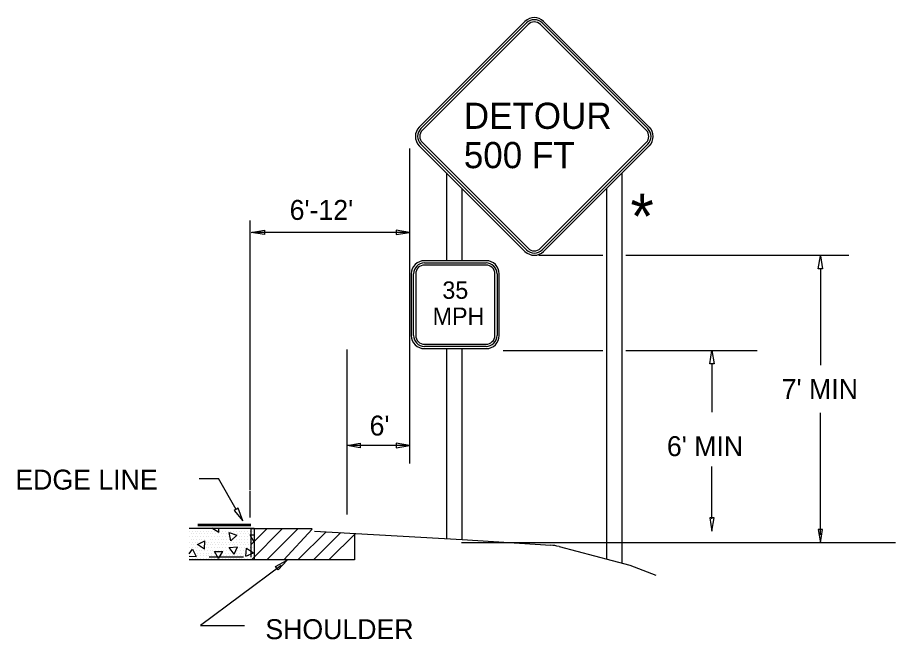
# Model space of a CAD drawing. Extents: x 12.65 to 19.62, y 5.94 to 15.74.
# Drawn here: x 15.864 to 18.505, y 10.963 to 12.834 of the extents above; entities that cross this region are included whole.
import ezdxf

# ---------------------------------------------------------------- set-up
doc = ezdxf.new("R2010")
doc.units = 0
for name, color, linetype in [('DETL-DIMS', 7, 'Continuous'), ('DETL-LINE', 7, 'Continuous'), ('DETL-NOTE', 7, 'Continuous')]:
    doc.layers.add(name, color=color, linetype=linetype)

msp = doc.modelspace()

# ---------------------------------------------------------------- linework, layer by layer
at = {"layer": 'DETL-DIMS'}
for p, q in [((17.0431, 12.4404), (17.0431, 11.4922)), ((16.5641, 11.4122), (16.5641, 12.2237)), ((17.0431, 12.1875), (16.5696, 12.1875)), ((17.4325, 12.1187), (17.6246, 12.1187)), ((17.6944, 12.1187), (18.3653, 12.1187)), ((18.2796, 12.0776), (18.2796, 11.7879)), ((16.8556, 11.3388), (16.8556, 11.8354)), ((17.3252, 11.8319), (17.6246, 11.8319)), ((17.6944, 11.8319), (18.0896, 11.8319)), ((17.9532, 11.7923), (17.9532, 11.6463)), ((18.2796, 11.2776), (18.2796, 11.6448)), ((17.0431, 11.5464), (16.8556, 11.5464)), ((17.9532, 11.3253), (17.9532, 11.4831)), ((16.4107, 11.4467), (16.4686, 11.4467)), ((16.5218, 11.3543), (16.4686, 11.4467)), ((16.5641, 11.3297), (16.5641, 11.4087)), ((16.6572, 11.1852), (16.4146, 11.0046)), ((16.4146, 11.0046), (16.5469, 11.0046))]:
    msp.add_line(p, q, dxfattribs=at)
for points in [[(16.607, 12.194), (16.607, 12.1808), (16.5674, 12.1874)], [(17.0035, 12.1941), (17.0035, 12.1809), (17.0431, 12.1875)], [(18.2862, 12.0776), (18.273, 12.0776), (18.2796, 12.1172)], [(17.9598, 11.7923), (17.9466, 11.7923), (17.9532, 11.8319)], [(16.8952, 11.553), (16.8952, 11.5398), (16.8556, 11.5464)], [(17.0035, 11.553), (17.0035, 11.5398), (17.0431, 11.5464)], [(16.5275, 11.3575), (16.516, 11.351), (16.5415, 11.32)], [(17.9598, 11.3283), (17.9466, 11.3283), (17.9532, 11.2887)], [(18.2862, 11.2934), (18.273, 11.2934), (18.2796, 11.2538)], [(16.648, 11.1719), (16.6398, 11.1823), (16.6752, 11.2013)]]:
    msp.add_lwpolyline(points, close=True, dxfattribs=at)
at = {"layer": 'DETL-LINE'}
for p, q in [((17.3908, 12.8224), (17.0728, 12.5044)), ((17.0775, 12.4998), (17.3954, 12.8177)), ((17.4001, 12.813), (17.0822, 12.495)), ((17.7555, 12.495), (17.4376, 12.813)), ((17.4422, 12.8177), (17.7602, 12.4998)), ((17.7648, 12.5044), (17.4469, 12.8224)), ((17.0728, 12.4483), (17.3908, 12.1303)), ((17.3954, 12.135), (17.0775, 12.453)), ((17.0822, 12.4576), (17.4001, 12.1397)), ((17.4376, 12.1397), (17.7555, 12.4576)), ((17.7602, 12.453), (17.4422, 12.135)), ((17.4469, 12.1303), (17.7648, 12.4483)), ((17.1543, 12.3668), (17.1543, 12.1024)), ((17.6834, 11.1924), (17.6834, 12.3668)), ((17.2021, 12.1024), (17.2021, 12.319)), ((17.6356, 12.319), (17.6356, 11.2049)), ((17.4375, 12.1396), (17.4376, 12.1397)), ((17.2736, 12.1024), (17.0884, 12.1024)), ((17.0884, 12.0958), (17.2736, 12.0958)), ((17.2736, 12.0892), (17.0884, 12.0892)), ((17.0488, 12.0628), (17.0488, 11.8776)), ((17.0554, 11.8776), (17.0554, 12.0628)), ((17.062, 12.0628), (17.062, 11.8776)), ((17.3, 11.8776), (17.3, 12.0628)), ((17.3066, 12.0628), (17.3066, 11.8776)), ((17.3133, 11.8776), (17.3133, 12.0628)), ((17.3, 11.8776), (17.3, 11.8776)), ((17.0884, 11.8511), (17.2736, 11.8511)), ((17.2736, 11.8445), (17.0884, 11.8445)), ((17.0884, 11.8379), (17.2736, 11.8379)), ((17.1543, 11.8379), (17.1543, 11.2664)), ((17.2021, 11.2635), (17.2021, 11.8379)), ((16.5662, 11.3084), (16.4063, 11.3084)), ((16.5662, 11.3064), (16.4063, 11.3064)), ((16.5662, 11.3044), (16.4063, 11.3044)), ((16.576, 11.2968), (16.3805, 11.2968)), ((16.3818, 11.2885), (16.3818, 11.2885)), ((16.386, 11.2802), (16.386, 11.2802)), ((16.3901, 11.2885), (16.3901, 11.2885)), ((16.3942, 11.2802), (16.3942, 11.2802)), ((16.3983, 11.2885), (16.3983, 11.2885)), ((16.4024, 11.2802), (16.4024, 11.2802)), ((16.4066, 11.2885), (16.4066, 11.2885)), ((16.4107, 11.2802), (16.4107, 11.2802)), ((16.4148, 11.2885), (16.4148, 11.2885)), ((16.419, 11.2802), (16.419, 11.2802)), ((16.4231, 11.2885), (16.4231, 11.2885)), ((16.4272, 11.2802), (16.4272, 11.2802)), ((16.4314, 11.2885), (16.4314, 11.2885)), ((16.4355, 11.2802), (16.4355, 11.2802)), ((16.4396, 11.2885), (16.4396, 11.2885)), ((16.4438, 11.2802), (16.4438, 11.2802)), ((16.4479, 11.2885), (16.4479, 11.2885)), ((16.4698, 11.2848), (16.4484, 11.2973)), ((16.4521, 11.2802), (16.4521, 11.2802)), ((16.4562, 11.2885), (16.4562, 11.2885)), ((16.4603, 11.2802), (16.4603, 11.2802)), ((16.4686, 11.2802), (16.4686, 11.2802)), ((16.4698, 11.2848), (16.4698, 11.2968)), ((16.4728, 11.2885), (16.4728, 11.2885)), ((16.4769, 11.2802), (16.4769, 11.2802)), ((16.481, 11.2885), (16.481, 11.2885)), ((16.4852, 11.2802), (16.4852, 11.2802)), ((16.4893, 11.2885), (16.4893, 11.2885)), ((16.4934, 11.2802), (16.4934, 11.2802)), ((16.4976, 11.2885), (16.4976, 11.2885)), ((16.5008, 11.2844), (16.5243, 11.2765)), ((16.5056, 11.26), (16.5008, 11.2844)), ((16.5058, 11.2885), (16.5058, 11.2885)), ((16.5141, 11.2885), (16.5141, 11.2885)), ((16.5182, 11.2802), (16.5182, 11.2802)), ((16.5224, 11.2885), (16.5224, 11.2885)), ((16.5265, 11.2802), (16.5265, 11.2802)), ((16.5306, 11.2885), (16.5306, 11.2885)), ((16.5347, 11.2802), (16.5347, 11.2802)), ((16.5388, 11.2885), (16.5388, 11.2885)), ((16.543, 11.2802), (16.543, 11.2802)), ((16.5471, 11.2885), (16.5471, 11.2885)), ((16.5512, 11.2802), (16.5512, 11.2802)), ((16.5554, 11.2885), (16.5554, 11.2885)), ((16.5595, 11.2802), (16.5595, 11.2802)), ((16.5636, 11.2885), (16.5636, 11.2885)), ((16.5668, 11.2964), (16.7505, 11.2964)), ((16.5668, 11.2484), (16.6149, 11.2964)), ((16.5668, 11.2102), (16.5668, 11.2948)), ((16.5675, 11.2024), (16.6615, 11.2964)), ((16.5678, 11.2802), (16.5678, 11.2802)), ((16.5719, 11.2885), (16.5719, 11.2885)), ((16.576, 11.2968), (16.576, 11.2968)), ((16.576, 11.2968), (16.576, 11.2019)), ((16.6142, 11.2024), (16.7082, 11.2964)), ((16.7501, 11.2947), (16.6653, 11.2024)), ((16.7075, 11.2024), (16.7922, 11.287)), ((16.7542, 11.2024), (16.8363, 11.2846)), ((16.7575, 11.289), (17.2021, 11.2635)), ((16.8008, 11.2024), (16.8804, 11.282)), ((16.878, 11.2831), (16.878, 11.2024)), ((16.3818, 11.2721), (16.3818, 11.2721)), ((16.3818, 11.2555), (16.3818, 11.2555)), ((16.386, 11.2638), (16.386, 11.2638)), ((16.3901, 11.2721), (16.3901, 11.2721)), ((16.3901, 11.2555), (16.3901, 11.2555)), ((16.3942, 11.2638), (16.3942, 11.2638)), ((16.3983, 11.2721), (16.3983, 11.2721)), ((16.3983, 11.2555), (16.3983, 11.2555)), ((16.4024, 11.2638), (16.4024, 11.2638)), ((16.4055, 11.2482), (16.4277, 11.2594)), ((16.4066, 11.2721), (16.4066, 11.2721)), ((16.4066, 11.2555), (16.4066, 11.2555)), ((16.4107, 11.2638), (16.4107, 11.2638)), ((16.4148, 11.2721), (16.4148, 11.2721)), ((16.4148, 11.2555), (16.4148, 11.2555)), ((16.419, 11.2638), (16.419, 11.2638)), ((16.4231, 11.2721), (16.4231, 11.2721)), ((16.4264, 11.2347), (16.4277, 11.2594)), ((16.4272, 11.2638), (16.4272, 11.2638)), ((16.4314, 11.2721), (16.4314, 11.2721)), ((16.4314, 11.2555), (16.4314, 11.2555)), ((16.4396, 11.2721), (16.4396, 11.2721)), ((16.4396, 11.2555), (16.4396, 11.2555)), ((16.4438, 11.2638), (16.4438, 11.2638)), ((16.4479, 11.2721), (16.4479, 11.2721)), ((16.4479, 11.2555), (16.4479, 11.2555)), ((16.4521, 11.2638), (16.4521, 11.2638)), ((16.4562, 11.2721), (16.4562, 11.2721)), ((16.4562, 11.2555), (16.4562, 11.2555)), ((16.4603, 11.2638), (16.4603, 11.2638)), ((16.4645, 11.2721), (16.4645, 11.2721)), ((16.4645, 11.2555), (16.4645, 11.2555)), ((16.4686, 11.2638), (16.4686, 11.2638)), ((16.4728, 11.2721), (16.4728, 11.2721)), ((16.4728, 11.2555), (16.4728, 11.2555)), ((16.4769, 11.2638), (16.4769, 11.2638)), ((16.481, 11.2721), (16.481, 11.2721)), ((16.481, 11.2555), (16.481, 11.2555)), ((16.4852, 11.2638), (16.4852, 11.2638)), ((16.4893, 11.2721), (16.4893, 11.2721)), ((16.4893, 11.2555), (16.4893, 11.2555)), ((16.4934, 11.2638), (16.4934, 11.2638)), ((16.4976, 11.2721), (16.4976, 11.2721)), ((16.4976, 11.2555), (16.4976, 11.2555)), ((16.5017, 11.2638), (16.5017, 11.2638)), ((16.5056, 11.26), (16.5243, 11.2765)), ((16.5058, 11.2555), (16.5058, 11.2555)), ((16.5141, 11.2642), (16.5141, 11.2642)), ((16.5141, 11.2555), (16.5141, 11.2555)), ((16.5224, 11.2722), (16.5224, 11.2722)), ((16.5224, 11.2642), (16.5224, 11.2642)), ((16.5224, 11.2555), (16.5224, 11.2555)), ((16.5306, 11.2722), (16.5306, 11.2722)), ((16.5306, 11.2642), (16.5306, 11.2642)), ((16.5306, 11.2555), (16.5306, 11.2555)), ((16.5388, 11.2722), (16.5388, 11.2722)), ((16.5388, 11.2642), (16.5388, 11.2642)), ((16.5388, 11.2555), (16.5388, 11.2555)), ((16.5471, 11.2722), (16.5471, 11.2722)), ((16.5471, 11.2642), (16.5471, 11.2642)), ((16.5471, 11.2555), (16.5471, 11.2555)), ((16.5554, 11.2722), (16.5554, 11.2722)), ((16.5554, 11.2642), (16.5554, 11.2642)), ((16.5554, 11.2555), (16.5554, 11.2555)), ((16.5636, 11.2774), (16.576, 11.2774)), ((16.576, 11.256), (16.5636, 11.2774)), ((16.5636, 11.2722), (16.5636, 11.2722)), ((16.5636, 11.2642), (16.5636, 11.2642)), ((16.5636, 11.2555), (16.5636, 11.2555)), ((16.5719, 11.2555), (16.5719, 11.2555)), ((17.1995, 11.2541), (18.5053, 11.2541)), ((17.2021, 11.2635), (17.4681, 11.2464)), ((16.3805, 11.2202), (16.3903, 11.2345)), ((16.3818, 11.239), (16.3818, 11.239)), ((16.386, 11.2472), (16.386, 11.2472)), ((16.386, 11.2307), (16.386, 11.2307)), ((16.3901, 11.239), (16.3901, 11.239)), ((16.3903, 11.2345), (16.4011, 11.2122)), ((16.3942, 11.2472), (16.3942, 11.2472)), ((16.3942, 11.2307), (16.3942, 11.2307)), ((16.3983, 11.239), (16.3983, 11.239)), ((16.4024, 11.2472), (16.4024, 11.2472)), ((16.4024, 11.2307), (16.4024, 11.2307)), ((16.4264, 11.2347), (16.4055, 11.2482)), ((16.4066, 11.239), (16.4066, 11.239)), ((16.4107, 11.2307), (16.4107, 11.2307)), ((16.4148, 11.239), (16.4148, 11.239)), ((16.419, 11.2307), (16.419, 11.2307)), ((16.4272, 11.2472), (16.4272, 11.2472)), ((16.4272, 11.2307), (16.4272, 11.2307)), ((16.4314, 11.239), (16.4314, 11.239)), ((16.4355, 11.2472), (16.4355, 11.2472)), ((16.4355, 11.2307), (16.4355, 11.2307)), ((16.4396, 11.239), (16.4396, 11.239)), ((16.4438, 11.2472), (16.4438, 11.2472)), ((16.4438, 11.2307), (16.4438, 11.2307)), ((16.4479, 11.239), (16.4479, 11.239)), ((16.4521, 11.2472), (16.4521, 11.2472)), ((16.4521, 11.2307), (16.4521, 11.2307)), ((16.4562, 11.239), (16.4562, 11.239)), ((16.4567, 11.2276), (16.4814, 11.2276)), ((16.4691, 11.2062), (16.4567, 11.2276)), ((16.4603, 11.2472), (16.4603, 11.2472)), ((16.4603, 11.2307), (16.4603, 11.2307)), ((16.4645, 11.239), (16.4645, 11.239)), ((16.4686, 11.2472), (16.4686, 11.2472)), ((16.4686, 11.2307), (16.4686, 11.2307)), ((16.4691, 11.2062), (16.4814, 11.2276)), ((16.4728, 11.239), (16.4728, 11.239)), ((16.4769, 11.2472), (16.4769, 11.2472)), ((16.4769, 11.2307), (16.4769, 11.2307)), ((16.481, 11.239), (16.481, 11.239)), ((16.4852, 11.2472), (16.4852, 11.2472)), ((16.4852, 11.2307), (16.4852, 11.2307)), ((16.4893, 11.239), (16.4893, 11.239)), ((16.4934, 11.2472), (16.4934, 11.2472)), ((16.4934, 11.2307), (16.4934, 11.2307)), ((16.4976, 11.239), (16.4976, 11.239)), ((16.5012, 11.2397), (16.5258, 11.2419)), ((16.5154, 11.2194), (16.5012, 11.2397)), ((16.5017, 11.2472), (16.5017, 11.2472)), ((16.5017, 11.2307), (16.5017, 11.2307)), ((16.51, 11.2472), (16.51, 11.2472)), ((16.5154, 11.2194), (16.5258, 11.2419)), ((16.5182, 11.2472), (16.5182, 11.2472)), ((16.5265, 11.2472), (16.5265, 11.2472)), ((16.5265, 11.2307), (16.5265, 11.2307)), ((16.5306, 11.239), (16.5306, 11.239)), ((16.5347, 11.2472), (16.5347, 11.2472)), ((16.5347, 11.2307), (16.5347, 11.2307)), ((16.5388, 11.239), (16.5388, 11.239)), ((16.543, 11.2472), (16.543, 11.2472)), ((16.543, 11.2307), (16.543, 11.2307)), ((16.5471, 11.239), (16.5471, 11.239)), ((16.5512, 11.2472), (16.5512, 11.2472)), ((16.5512, 11.213), (16.553, 11.2378)), ((16.5512, 11.2307), (16.5512, 11.2307)), ((16.553, 11.2378), (16.5736, 11.2239)), ((16.5554, 11.239), (16.5554, 11.239)), ((16.5595, 11.2472), (16.5595, 11.2472)), ((16.5636, 11.239), (16.5636, 11.239)), ((16.5678, 11.2472), (16.5678, 11.2472)), ((16.5678, 11.2307), (16.5678, 11.2307)), ((16.5719, 11.239), (16.5719, 11.239)), ((17.4932, 11.2423), (17.7067, 11.1863)), ((16.3805, 11.2137), (16.4011, 11.2122)), ((16.576, 11.2019), (16.3805, 11.2019)), ((16.3818, 11.2224), (16.3818, 11.2224)), ((16.3818, 11.2059), (16.3818, 11.2059)), ((16.3901, 11.2059), (16.3901, 11.2059)), ((16.3983, 11.2224), (16.3983, 11.2224)), ((16.3983, 11.2059), (16.3983, 11.2059)), ((16.4066, 11.2224), (16.4066, 11.2224)), ((16.4066, 11.2144), (16.4066, 11.2144)), ((16.4066, 11.2059), (16.4066, 11.2059)), ((16.4148, 11.2224), (16.4148, 11.2224)), ((16.4148, 11.2144), (16.4148, 11.2144)), ((16.4148, 11.2059), (16.4148, 11.2059)), ((16.4231, 11.2224), (16.4231, 11.2224)), ((16.4231, 11.2144), (16.4231, 11.2144)), ((16.4231, 11.2059), (16.4231, 11.2059)), ((16.4314, 11.2224), (16.4314, 11.2224)), ((16.4314, 11.2144), (16.4314, 11.2144)), ((16.4314, 11.2059), (16.4314, 11.2059)), ((16.4396, 11.2224), (16.4396, 11.2224)), ((16.4396, 11.2144), (16.4396, 11.2144)), ((16.4396, 11.2059), (16.4396, 11.2059)), ((16.5438, 11.2102), (16.4405, 11.2102)), ((16.4479, 11.2224), (16.4479, 11.2224)), ((16.4479, 11.2144), (16.4479, 11.2144)), ((16.4479, 11.2059), (16.4479, 11.2059)), ((16.4562, 11.2224), (16.4562, 11.2224)), ((16.4562, 11.2144), (16.4562, 11.2144)), ((16.4562, 11.2059), (16.4562, 11.2059)), ((16.4645, 11.2059), (16.4645, 11.2059)), ((16.4728, 11.2059), (16.4728, 11.2059)), ((16.4769, 11.2142), (16.4769, 11.2142)), ((16.481, 11.2224), (16.481, 11.2224)), ((16.481, 11.2059), (16.481, 11.2059)), ((16.4852, 11.2142), (16.4852, 11.2142)), ((16.4893, 11.2224), (16.4893, 11.2224)), ((16.4893, 11.2059), (16.4893, 11.2059)), ((16.4934, 11.2142), (16.4934, 11.2142)), ((16.4976, 11.2224), (16.4976, 11.2224)), ((16.4976, 11.2059), (16.4976, 11.2059)), ((16.5017, 11.2142), (16.5017, 11.2142)), ((16.5058, 11.2224), (16.5058, 11.2224)), ((16.5058, 11.2059), (16.5058, 11.2059)), ((16.51, 11.2142), (16.51, 11.2142)), ((16.5141, 11.2059), (16.5141, 11.2059)), ((16.5182, 11.2142), (16.5182, 11.2142)), ((16.5224, 11.2224), (16.5224, 11.2224)), ((16.5224, 11.2059), (16.5224, 11.2059)), ((16.5265, 11.2142), (16.5265, 11.2142)), ((16.5306, 11.2224), (16.5306, 11.2224)), ((16.5306, 11.2059), (16.5306, 11.2059)), ((16.5347, 11.2142), (16.5347, 11.2142)), ((16.5388, 11.2224), (16.5388, 11.2224)), ((16.5388, 11.2059), (16.5388, 11.2059)), ((16.543, 11.2142), (16.543, 11.2142)), ((16.7505, 11.2024), (16.5438, 11.2024)), ((16.5471, 11.2224), (16.5471, 11.2224)), ((16.5471, 11.2059), (16.5471, 11.2059)), ((16.5512, 11.213), (16.5736, 11.2239)), ((16.5512, 11.2142), (16.5512, 11.2142)), ((16.5554, 11.2059), (16.5554, 11.2059)), ((16.5595, 11.2142), (16.5595, 11.2142)), ((16.5636, 11.2059), (16.5636, 11.2059)), ((16.5678, 11.2142), (16.5678, 11.2142)), ((16.5719, 11.2224), (16.5719, 11.2224)), ((16.5719, 11.2059), (16.5719, 11.2059)), ((16.878, 11.2024), (16.6219, 11.2024)), ((17.7067, 11.1863), (17.7844, 11.1566))]:
    msp.add_line(p, q, dxfattribs=at)
for centre, radius, start, end in [((17.4188, 12.7943), 0.0397, 45, 135), ((17.4188, 12.7943), 0.0331, 45, 135), ((17.4188, 12.7943), 0.0265, 45, 135), ((17.1008, 12.4764), 0.0397, 135, 225), ((17.1008, 12.4764), 0.0331, 135, 225), ((17.1008, 12.4764), 0.0265, 135, 225), ((17.7368, 12.4764), 0.0265, 315, 45), ((17.7368, 12.4764), 0.0331, 315, 45), ((17.7368, 12.4764), 0.0397, 315, 45), ((17.4188, 12.1584), 0.0397, 225, 315), ((17.4188, 12.1584), 0.0331, 225, 315), ((17.4188, 12.1584), 0.0265, 225, 315), ((17.0884, 12.0628), 0.0397, 90, 180), ((17.2736, 12.0628), 0.0397, 360, 90), ((17.0884, 12.0628), 0.0331, 90, 180), ((17.0884, 12.0628), 0.0265, 90, 180), ((17.2736, 12.0628), 0.0331, 360, 90), ((17.2736, 12.0628), 0.0265, 360, 90), ((17.0884, 11.8776), 0.0397, 180, 270), ((17.0884, 11.8776), 0.0331, 180, 270), ((17.0884, 11.8776), 0.0265, 180, 270), ((17.2736, 11.8776), 0.0397, 270, 360), ((17.2736, 11.8776), 0.0331, 270, 360), ((17.2736, 11.8776), 0.0265, 270, 360), ((17.4596, 11.1144), 0.1323, 75.2872, 86.2969)]:
    msp.add_arc(centre, radius, start, end, dxfattribs=at)

# ---------------------------------------------------------------- texts
for s, height, p in [('DETOUR', 0.07876, (17.2067, 12.4991)), ('500 FT', 0.07876, (17.2067, 12.3808)), ('35', 0.05236, (17.1422, 11.9877)), ('MPH', 0.05236, (17.113, 11.9092))]:
    msp.add_text(s, height=height, rotation=360, dxfattribs=at).set_placement(p)
at = {"layer": 'DETL-NOTE'}
for s, height, p in [("6'-12'", 0.06, (16.6828, 12.2252)), ('*', 0.135, (17.7081, 12.1687)), ("7' MIN", 0.06, (18.1631, 11.6864)), ("6'", 0.06, (16.9233, 11.5763)), ("6' MIN", 0.06, (17.8177, 11.5144)), ('EDGE LINE', 0.06, (15.8576, 11.4137)), ('SHOULDER', 0.06, (16.6097, 10.9637))]:
    msp.add_text(s, height=height, rotation=360, dxfattribs=at).set_placement(p)

doc.saveas('drawing.dxf')
